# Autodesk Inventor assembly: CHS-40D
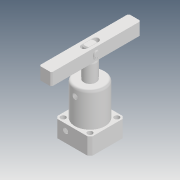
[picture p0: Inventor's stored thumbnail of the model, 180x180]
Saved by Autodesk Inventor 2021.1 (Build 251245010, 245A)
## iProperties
Created: 2019-04
Part Number: CHS-40D
Description: STEP AP203
Document SubType Name: Assembly
Designer: user
Title: chs-40d_asm.STEP
Revision Number: ÈÎºÎ
Sending System: SolidWorks 2017
Preprocessor: SwSTEP 2.0
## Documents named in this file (6)
- D:\Vault_2016\Projekty\Clamptek\Hydraulic\CHS\CHS-40\Inventor\CHS-40D\CHS-40D.iam
- D:\Vault_2016\Projekty\Clamptek\Hydraulic\CHS\CHS-40\Inventor\CHS-40D\CHS-40-03.ipt
- D:\Vault_2016\Projekty\Clamptek\Hydraulic\CHS\CHS-40\Inventor\CHS-40D\CHS-40D-02.ipt
- D:\Vault_2016\Projekty\Clamptek\Hydraulic\CHS\CHS-40\Inventor\CHS-40D\CHS-40D-01.ipt
- D:\Vault_2016\Projekty\Clamptek\Hydraulic\CHS\CHS-40\Inventor\CHS-40D\12ÖáÓÃµ²È¦.ipt
- D:\Vault_2016\Projekty\Clamptek\Hydraulic\CHS\CHS-40\Inventor\CHS-40D\XIAO.ipt
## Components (6 placed, 6 different names)
1. CHS-40-03_1
2. CHS-40D-02_2
3. CHS-40D-01_3
4. 12ÖáÓÃµ²È¦_4
5. XIAO_5
6. 12ÖáÓÃµ²È¦_6
